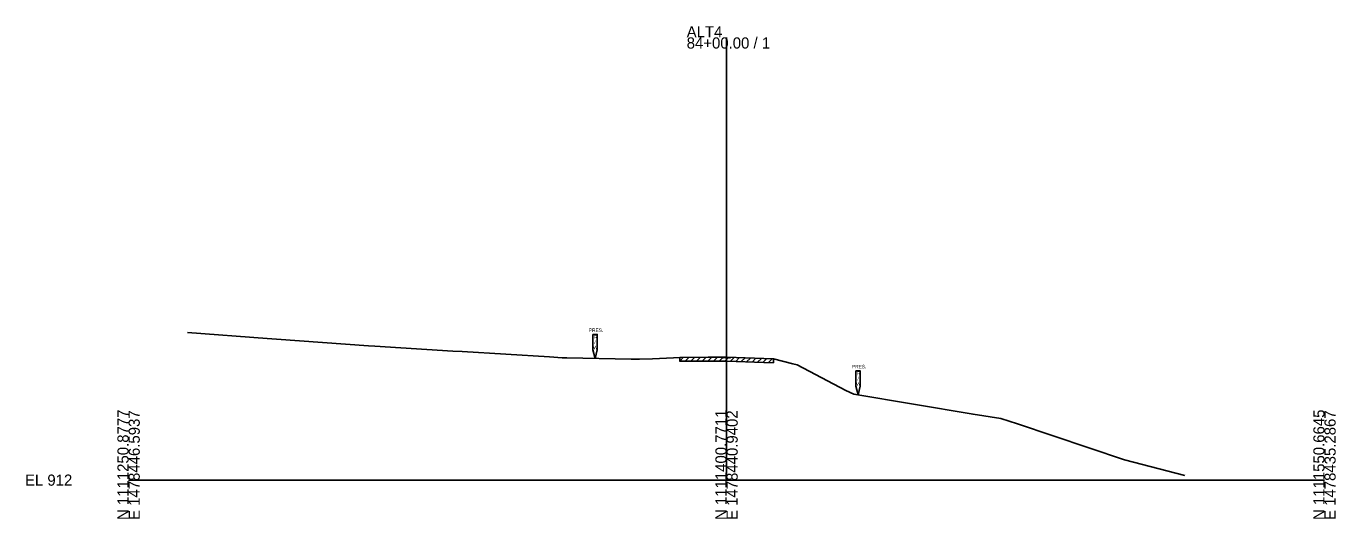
# Model space of a CAD drawing. Extents: x -26 to 1303, y -10 to 19562.
# Drawn here: x -25.7 to 302.8, y 490.3 to 613.8 of the extents above; entities that cross this region are included whole.
import ezdxf

# ---------------------------------------------------------------- set-up
doc = ezdxf.new("R2010")
doc.units = 0
for name, color, linetype in [('RD_GPK_XS_Cell', 7, 'Continuous'), ('RD_XS_ExGround', 7, 'Continuous'), ('RD_XS_ExPaveRet', 7, 'Continuous'), ('RD_XS_ExRW', 7, 'Continuous'), ('RD_XS_TX_Elev_EX', 7, 'Continuous')]:
    doc.layers.add(name, color=color, linetype=linetype)

msp = doc.modelspace()

# ---------------------------------------------------------------- linework, layer by layer
at = {"layer": 'RD_GPK_XS_Cell'}
for p, q in [((150, 500), (150, 610.98)), ((0, 500), (150, 500)), ((150, 500), (300, 500))]:
    msp.add_line(p, q, dxfattribs=at)
at = {"layer": 'RD_XS_ExGround'}
msp.add_lwpolyline([(14.81, 536.99), (34.76, 535.54), (37.06, 535.37), (60.22, 533.68), (61.77, 533.57), (81.31, 532.36), (83.7, 532.22), (105.58, 530.87), (108.76, 530.69), (109.93, 530.63), (126.1, 530.33), (128.2, 530.28), (131.44, 530.42), (136.69, 530.64), (138.24, 530.77), (145.43, 530.82), (150.05, 530.84), (159.38, 530.49), (161.76, 530.39), (166.63, 529.19), (167.68, 528.94), (179.89, 522.48), (181.93, 521.56), (211.86, 516.52), (218.81, 515.44), (223.03, 514.15), (249.84, 505.11), (264.93, 501.15)], dxfattribs=at)
at = {"layer": 'RD_XS_ExPaveRet'}
for p, q in [((138.24, 529.82), (139.2, 530.78)), ((138.24, 530.77), (138.24, 529.77)), ((139.62, 529.79), (140.62, 530.79)), ((141.04, 529.79), (142.04, 530.8)), ((142.46, 529.8), (143.47, 530.8)), ((143.89, 529.81), (144.89, 530.81)), ((145.31, 529.82), (146.31, 530.82)), ((146.73, 529.83), (147.73, 530.83)), ((148.15, 529.83), (149.15, 530.83)), ((149.57, 529.84), (150.55, 530.82)), ((150.95, 529.81), (151.91, 530.77)), ((152.32, 529.76), (153.28, 530.72)), ((153.68, 529.7), (154.64, 530.66)), ((155.04, 529.65), (156, 530.61)), ((156.41, 529.6), (157.36, 530.56)), ((157.77, 529.55), (158.73, 530.51)), ((159.13, 529.5), (160.09, 530.46)), ((160.49, 529.45), (161.45, 530.41)), ((161.76, 530.39), (161.76, 529.39))]:
    msp.add_line(p, q, dxfattribs=at)
msp.add_lwpolyline([(138.24, 529.78), (145.44, 529.82), (150.04, 529.84), (159.35, 529.49), (161.76, 529.4)], dxfattribs=at)
at = {"layer": 'RD_XS_ExRW'}
for points in [[(116.45, 536.51), (117.55, 536.51), (117.55, 532.68), (117, 530.5), (116.45, 532.68)], [(182.45, 527.39), (183.55, 527.39), (183.55, 523.56), (183, 521.38), (182.45, 523.56)]]:
    msp.add_lwpolyline(points, close=True, dxfattribs=at)

# ---------------------------------------------------------------- texts
at = {"layer": 'RD_GPK_XS_Cell'}
for s, p in [('ALT4', (140, 610.98)), ('84+00.00 / 1', (140, 608.18)), ('EL 912', (-26, 498.6))]:
    msp.add_text(s, height=2.8, dxfattribs=at).set_placement(p)
for s, p in [('N 1111250.8777', (0, 490)), ('E 1478446.5937', (2.8, 490)), ('N 1111400.7711', (150, 490)), ('E 1478440.9402', (152.8, 490)), ('N 1111550.6645', (300, 490)), ('E 1478435.2867', (302.8, 490))]:
    msp.add_text(s, height=2.8, rotation=90, dxfattribs=at).set_placement(p)
at = {"layer": 'RD_XS_ExRW'}
for s, p in [('PRES.', (115.45, 537.14)), ('R', (116.71, 535.42)), ('W', (116.53, 532.8)), ('/', (116.83, 534.11)), ('PRES.', (181.45, 528.02)), ('R', (182.71, 526.3)), ('/', (182.83, 524.99)), ('W', (182.53, 523.67))]:
    msp.add_text(s, height=0.875, dxfattribs=at).set_placement(p)
at = {"layer": 'RD_XS_TX_Elev_EX'}
msp.add_text('942.84', height=0.5, dxfattribs=at).set_placement((148.98, 530.34))

doc.saveas('drawing.dxf')
